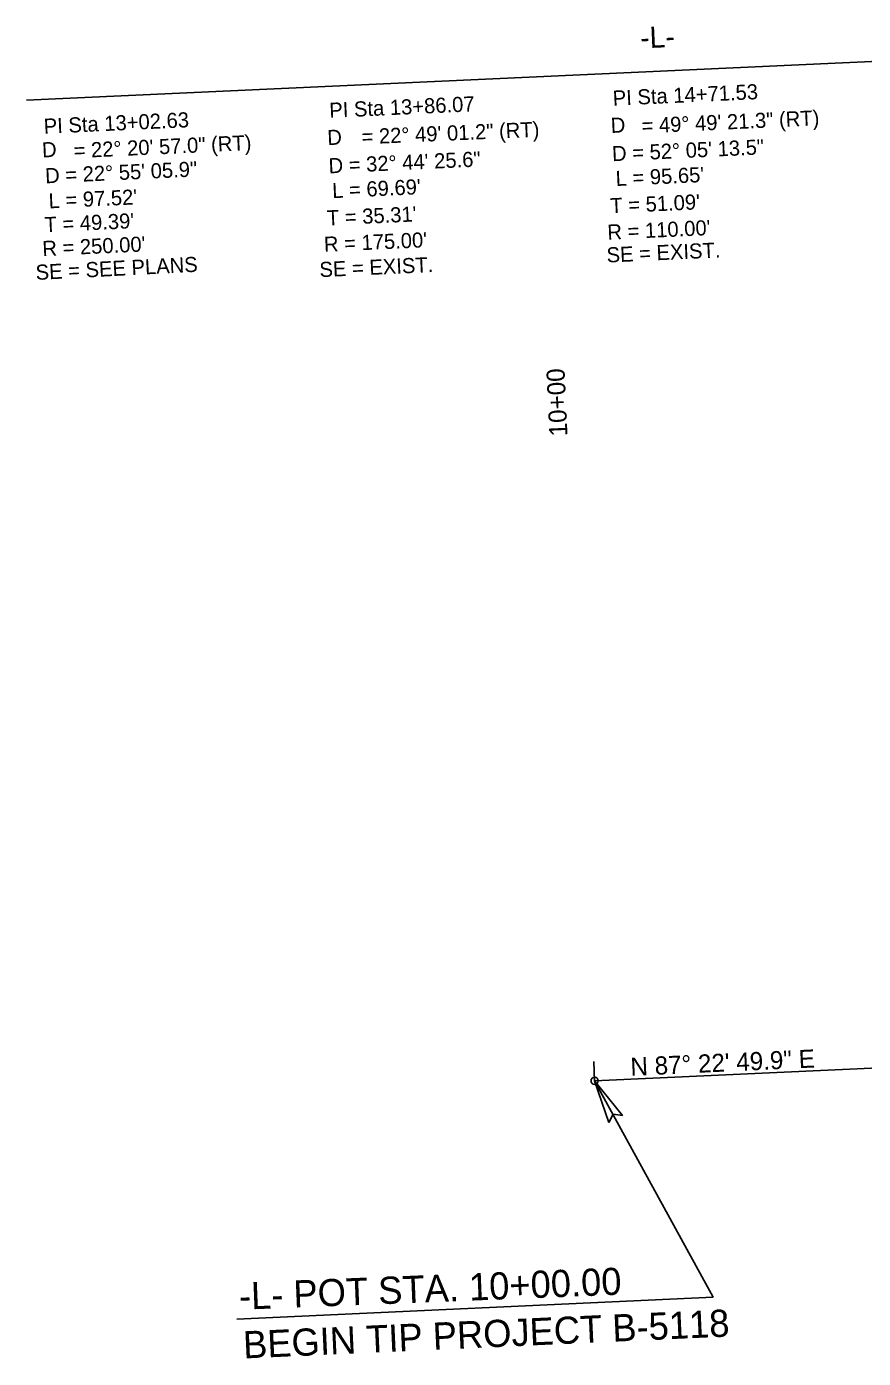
# Model space of a CAD drawing. Extents: x 1191189 to 1191812, y 892693 to 893370.
# Drawn here: x 1191188.9 to 1191327.5, y 893024 to 893244.4 of the extents above; entities that cross this region are included whole.
import ezdxf

# ---------------------------------------------------------------- set-up
doc = ezdxf.new("R2010")
doc.units = 0
for name, color, linetype in [('Prop Horizontal Alignment', 7, 'Continuous'), ('Prop Horizontal Alignment Curve and Spiral Data', 7, 'Continuous'), ('Prop Horizontal Alignment Direction Label', 7, 'Continuous'), ('Prop Horizontal Alignment Station Label', 7, 'Continuous'), ('Prop Horizontal Alignment Tick Label', 7, 'Continuous'), ('Prop Horizontal Alignment Tick Large', 7, 'Continuous'), ('Prop Leader Line Medium', 7, 'Continuous'), ('Prop Terminator CELL', 7, 'Continuous')]:
    doc.layers.add(name, color=color, linetype=linetype)

msp = doc.modelspace()

# ---------------------------------------------------------------- linework, layer by layer
at = {"layer": 'Prop Horizontal Alignment'}
msp.add_line((1191282.99, 893069.95), (1191535.97, 893081.52), dxfattribs=at)
at = {"layer": 'Prop Horizontal Alignment Curve and Spiral Data'}
msp.add_line((1191188.94, 893232.25), (1191421.22, 893242.88), dxfattribs=at)
at = {"layer": 'Prop Horizontal Alignment Station Label'}
msp.add_circle((1191282.99, 893069.95), 0.6, dxfattribs=at)
at = {"layer": 'Prop Horizontal Alignment Tick Large'}
msp.add_line((1191282.99, 893069.95), (1191282.85, 893073.15), dxfattribs=at)
at = {"layer": 'Prop Leader Line Medium'}
for p in [(1191282.99, 893069.95), (1191223.74, 893030.51)]:
    msp.add_line(p, (1191302.59, 893034.12), dxfattribs=at)
at = {"layer": 'Prop Terminator CELL'}
msp.add_lwpolyline([(1191285.36, 893063.04), (1191282.99, 893069.95), (1191287.59, 893064.21), (1191286.03, 893064.4)], close=True, dxfattribs=at)

# ---------------------------------------------------------------- texts
at = {"layer": 'Prop Horizontal Alignment Curve and Spiral Data'}
for s, height, rotation, p in [('-L-', 3.5, 2.5289, (1191290.6, 893240.83)), ('PI Sta 14+71.53', 2.5, 2.621, (1191286.04, 893231.34)), ('PI Sta 13+86.07', 2.5, 2.621, (1191239.11, 893229.33)), ('PI Sta 13+02.63', 2.5, 2.621, (1191191.83, 893226.69)), ('D', 2.5, 2.621, (1191285.71, 893226.83)), ('= 49%%d 49\' 21.3" (RT)', 2.5, 2.621, (1191290.81, 893226.77)), ('D', 2.5, 2.621, (1191238.78, 893224.82)), ('= 22%%d 49\' 01.2" (RT)', 2.5, 2.4459, (1191244.45, 893224.95)), ('D', 2.5, 2.621, (1191191.55, 893222.78)), ('= 22%%d 20\' 57.0" (RT)', 2.5, 2.621, (1191196.78, 893222.66)), ('D = 52%%d 05\' 13.5"', 2.5, 2.621, (1191285.92, 893222.15)), ('D = 32%%d 44\' 25.6"', 2.5, 2.621, (1191238.99, 893220.14)), ('D = 22%%d 55\' 05.9"', 2.5, 2.621, (1191192.06, 893218.49)), ("L = 95.65'", 2.5, 2.621, (1191286.52, 893218.05)), ("L = 69.69'", 2.5, 2.621, (1191239.59, 893216.04)), ("L = 97.52'", 2.5, 2.621, (1191192.64, 893214.35)), ("T = 51.09'", 2.5, 2.621, (1191285.63, 893213.53)), ("T = 49.39'", 2.5, 2.621, (1191191.96, 893210.4)), ("T = 35.31'", 2.5, 2.621, (1191238.71, 893211.52)), ("R = 110.00'", 2.5, 2.621, (1191285.15, 893209.16)), ("R = 250.00'", 2.5, 2.621, (1191191.6, 893206.45)), ("R = 175.00'", 2.5, 2.621, (1191238.22, 893207.15)), ('SE = EXIST.', 2.5, 2.621, (1191285.02, 893205.38)), ('SE = SEE PLANS', 2.5, 2.926, (1191190.5, 893202.5)), ('SE = EXIST.', 2.5, 2.621, (1191237.48, 893202.96))]:
    msp.add_text(s, height=height, rotation=rotation, dxfattribs=at).set_placement(p)
at = {"layer": 'Prop Horizontal Alignment Direction Label'}
msp.add_text('N 87%%d 22\' 49.9" E', height=3, rotation=2.6195, dxfattribs=at).set_placement((1191288.98, 893070.76))
at = {"layer": 'Prop Horizontal Alignment Tick Label'}
msp.add_text('10+00', height=3, rotation=92.6195, dxfattribs=at).set_placement((1191278.5, 893176.68))
at = {"layer": 'Prop Leader Line Medium'}
for s, rotation, p in [('-L- POT STA. 10+00.00', 2.2753, (1191224.18, 893032.04)), ('BEGIN TIP PROJECT B-5118', 2.5982, (1191224.88, 893023.98))]:
    msp.add_text(s, height=4.5, rotation=rotation, dxfattribs=at).set_placement(p)

doc.saveas('drawing.dxf')
